// Mitsubishi GX Works2 project: 54.正转N个脉冲反转N个脉冲停止   PLC: FX3U/FX3UC

PROGRAM MAIN
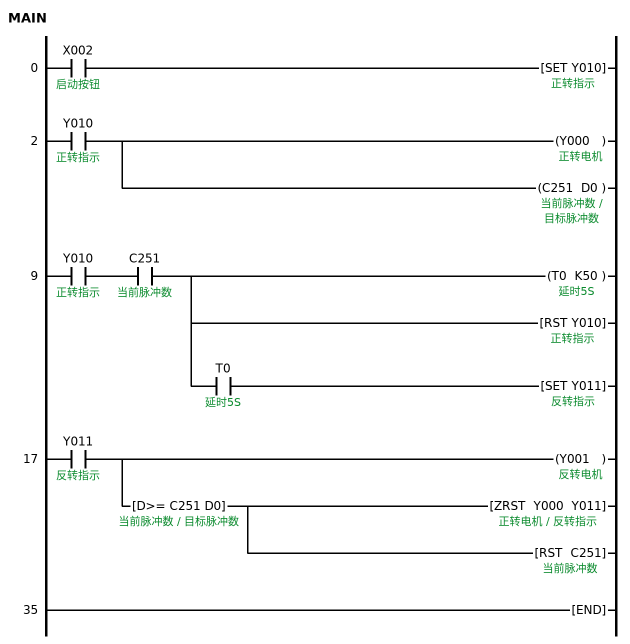
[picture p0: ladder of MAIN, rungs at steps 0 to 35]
0     LD      X002  ; 启动按钮
      SET     Y010  ; 正转指示
2     LD      Y010  ; 正转指示
      OUT     Y000  ; 正转电机
      OUT     C251 D0  ; 当前脉冲数 / 目标脉冲数
9     LD      Y010  ; 正转指示
      AND     C251  ; 当前脉冲数
      OUT     T0 K50  ; 延时5S
      RST     Y010  ; 正转指示
      AND     T0  ; 延时5S
      SET     Y011  ; 反转指示
17    LD      Y011  ; 反转指示
      OUT     Y001  ; 反转电机
      ANDD>=  C251 D0  ; 当前脉冲数 / 目标脉冲数
      ZRST    Y000 Y011
        [note] 反转完成重置所有电机和高速计数器
      RST     C251  ; 当前脉冲数
35    END
END_PROGRAM

// device comments not shown above
X000  ; x2
M0  ; 运行标识
